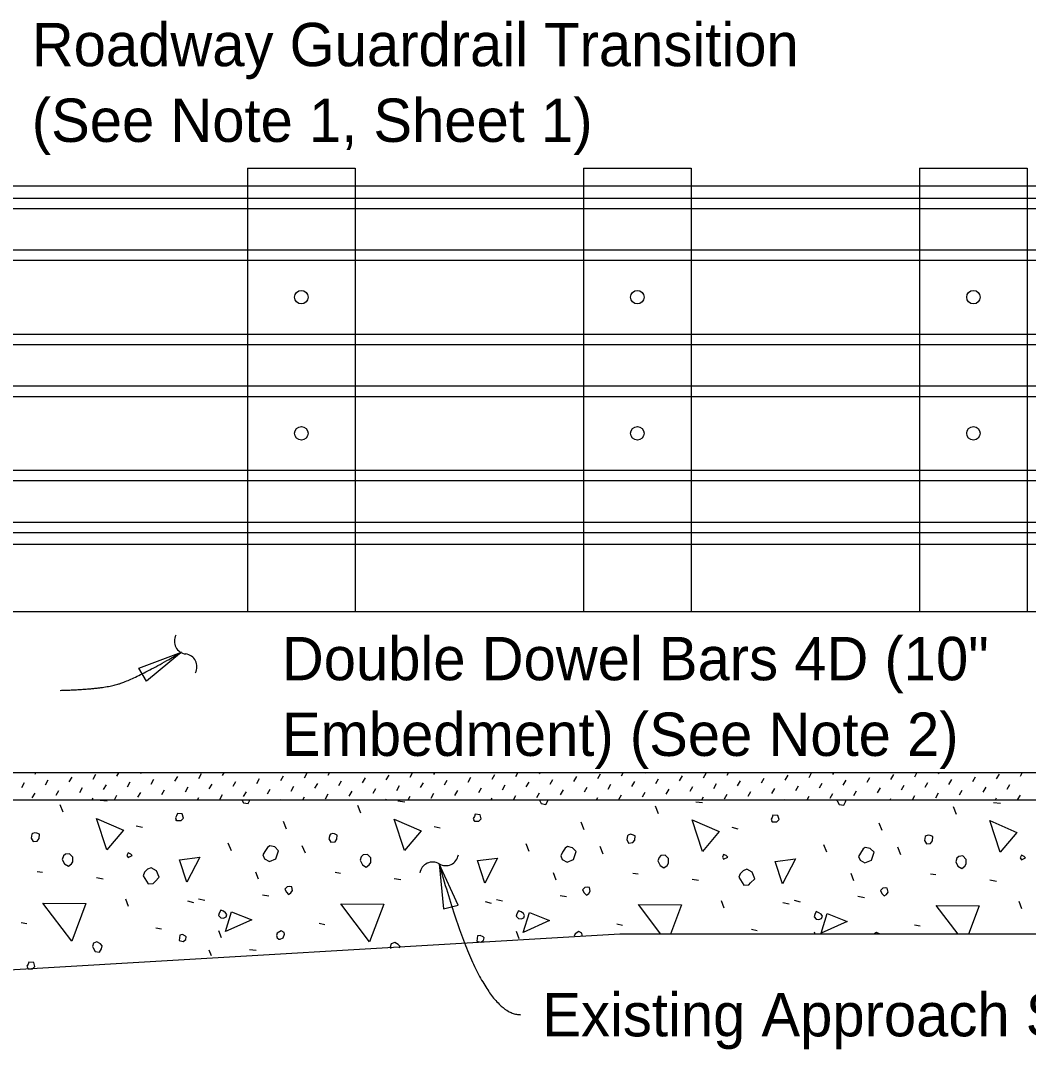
# Model space of a CAD drawing. Extents: x 21526.6 to 21595.9, y 56117 to 56157.3.
# Drawn here: x 21556.736 to 21561.422, y 56133.174 to 56137.959 of the extents above; entities that cross this region are included whole.
import ezdxf

# ---------------------------------------------------------------- set-up
doc = ezdxf.new("R2010")
doc.units = 0
for name, color, linetype in [('AdhocPoint_dp', 7, 'Continuous'), ('Border', 7, 'Continuous'), ('Patterning', 7, 'Continuous'), ('PlotBorder_dp', 7, 'Continuous'), ('SheetBorder_dp', 7, 'Continuous')]:
    doc.layers.add(name, color=color, linetype=linetype)

msp = doc.modelspace()

# ---------------------------------------------------------------- linework, layer by layer
at = {"layer": 'AdhocPoint_dp'}
for p, q in [((21554.3018, 56135.21), (21562.4118, 56135.21)), ((21565.8764, 56134.4601), (21554.3018, 56134.4601)), ((21554.3018, 56134.3351), (21565.8764, 56134.3351)), ((21559.5217, 56133.71), (21555.3017, 56133.4601)), ((21565.8764, 56133.71), (21559.5217, 56133.71))]:
    msp.add_line(p, q, dxfattribs=at)
at = {"layer": 'Patterning'}
for p, q in [((21557.7913, 56137.2725), (21557.7913, 56135.21)), ((21557.7913, 56137.2725), (21558.2913, 56137.2725)), ((21558.2913, 56137.2725), (21558.2913, 56135.21)), ((21559.3538, 56137.2725), (21559.3538, 56135.21)), ((21559.3538, 56137.2725), (21559.8538, 56137.2725)), ((21559.8538, 56137.2725), (21559.8538, 56135.21)), ((21560.9163, 56137.2725), (21560.9163, 56135.21)), ((21560.9163, 56137.2725), (21561.4163, 56137.2725)), ((21561.4163, 56137.2725), (21561.4163, 56135.21)), ((21552.8484, 56137.1336), (21564.1633, 56137.1336)), ((21552.8484, 56137.0853), (21564.1633, 56137.0853)), ((21552.8484, 56136.8925), (21564.1633, 56136.8925)), ((21552.8484, 56136.8443), (21564.1633, 56136.8443)), ((21552.8484, 56136.5003), (21564.1633, 56136.5003)), ((21552.8484, 56136.4521), (21564.1633, 56136.4521)), ((21552.8484, 56136.2593), (21564.1633, 56136.2593)), ((21552.8484, 56136.2112), (21564.1633, 56136.2112)), ((21552.8484, 56135.8672), (21564.1633, 56135.8672)), ((21552.8484, 56135.819), (21564.1633, 56135.819)), ((21552.8484, 56135.6262), (21564.1633, 56135.6262)), ((21552.8484, 56135.5779), (21564.1633, 56135.5779)), ((21556.803, 56134.4539), (21556.8066, 56134.4601)), ((21557.0731, 56134.431), (21557.086, 56134.4534)), ((21557.1837, 56134.4439), (21557.1931, 56134.4601)), ((21557.2943, 56134.4569), (21557.2962, 56134.4601)), ((21557.5644, 56134.434), (21557.5774, 56134.4564)), ((21557.6751, 56134.447), (21557.6827, 56134.4601)), ((21557.7857, 56134.4599), (21557.7858, 56134.4601)), ((21557.9452, 56134.424), (21557.9581, 56134.4464)), ((21558.0558, 56134.437), (21558.0688, 56134.4594)), ((21558.1664, 56134.45), (21558.1723, 56134.4601)), ((21558.4365, 56134.4271), (21558.4495, 56134.4495)), ((21558.5472, 56134.44), (21558.5588, 56134.4601)), ((21558.6578, 56134.453), (21558.6619, 56134.4601)), ((21558.9279, 56134.4301), (21558.9409, 56134.4525)), ((21559.0385, 56134.4431), (21559.0484, 56134.4601)), ((21559.1492, 56134.456), (21559.1515, 56134.4601)), ((21559.4193, 56134.4331), (21559.4322, 56134.4555)), ((21559.5299, 56134.4461), (21559.538, 56134.4601)), ((21559.6405, 56134.459), (21559.6412, 56134.4601)), ((21559.8, 56134.4232), (21559.813, 56134.4456)), ((21559.9106, 56134.4361), (21559.9236, 56134.4585)), ((21560.0213, 56134.4491), (21560.0276, 56134.4601)), ((21560.2914, 56134.4262), (21560.3043, 56134.4486)), ((21560.402, 56134.4391), (21560.4141, 56134.4601)), ((21560.5126, 56134.4521), (21560.5173, 56134.4601)), ((21560.7827, 56134.4292), (21560.7957, 56134.4516)), ((21560.8934, 56134.4422), (21560.9038, 56134.4601)), ((21561.004, 56134.4551), (21561.0069, 56134.4601)), ((21561.2741, 56134.4322), (21561.2871, 56134.4546)), ((21561.3847, 56134.4452), (21561.3934, 56134.4601)), ((21556.7412, 56134.3921), (21556.7541, 56134.4145)), ((21556.8518, 56134.405), (21556.8648, 56134.4274)), ((21556.9624, 56134.418), (21556.9754, 56134.4404)), ((21557.1219, 56134.3821), (21557.1349, 56134.4045)), ((21557.2325, 56134.3951), (21557.2455, 56134.4175)), ((21557.3432, 56134.4081), (21557.3561, 56134.4305)), ((21557.4538, 56134.421), (21557.4668, 56134.4434)), ((21557.6133, 56134.3852), (21557.6262, 56134.4075)), ((21557.7239, 56134.3981), (21557.7369, 56134.4205)), ((21557.8345, 56134.4111), (21557.8475, 56134.4335)), ((21557.994, 56134.3752), (21558.007, 56134.3976)), ((21558.1046, 56134.3882), (21558.1176, 56134.4106)), ((21558.2153, 56134.4011), (21558.2282, 56134.4235)), ((21558.3259, 56134.4141), (21558.3389, 56134.4365)), ((21558.4854, 56134.3782), (21558.4983, 56134.4006)), ((21558.596, 56134.3912), (21558.609, 56134.4136)), ((21558.7066, 56134.4042), (21558.7196, 56134.4266)), ((21558.8173, 56134.4171), (21558.8302, 56134.4395)), ((21558.9767, 56134.3813), (21558.9897, 56134.4036)), ((21559.0874, 56134.3942), (21559.1003, 56134.4166)), ((21559.198, 56134.4072), (21559.211, 56134.4296)), ((21559.3086, 56134.4201), (21559.3216, 56134.4425)), ((21559.4681, 56134.3843), (21559.4811, 56134.4067)), ((21559.5787, 56134.3972), (21559.5917, 56134.4196)), ((21559.6894, 56134.4102), (21559.7023, 56134.4326)), ((21559.9595, 56134.3873), (21559.9724, 56134.4097)), ((21560.0701, 56134.4003), (21560.0831, 56134.4226)), ((21560.1807, 56134.4132), (21560.1937, 56134.4356)), ((21560.3402, 56134.3774), (21560.3532, 56134.3997)), ((21560.4508, 56134.3903), (21560.4638, 56134.4127)), ((21560.5615, 56134.4033), (21560.5744, 56134.4257)), ((21560.6721, 56134.4162), (21560.6851, 56134.4386)), ((21560.8316, 56134.3804), (21560.8445, 56134.4028)), ((21560.9422, 56134.3933), (21560.9552, 56134.4157)), ((21561.0528, 56134.4063), (21561.0658, 56134.4287)), ((21561.1635, 56134.4193), (21561.1764, 56134.4417)), ((21561.3229, 56134.3834), (21561.3359, 56134.4058)), ((21556.79, 56134.3432), (21556.803, 56134.3656)), ((21556.9006, 56134.3562), (21556.9136, 56134.3786)), ((21557.0113, 56134.3692), (21557.0242, 56134.3916)), ((21557.1718, 56134.3351), (21557.1837, 56134.3557)), ((21557.2814, 56134.3463), (21557.2943, 56134.3687)), ((21557.392, 56134.3592), (21557.405, 56134.3816)), ((21557.5026, 56134.3722), (21557.5156, 56134.3946)), ((21557.6621, 56134.3363), (21557.6751, 56134.3587)), ((21557.7727, 56134.3493), (21557.7857, 56134.3717)), ((21557.8834, 56134.3623), (21557.8963, 56134.3846)), ((21558.1535, 56134.3393), (21558.1664, 56134.3617)), ((21558.2641, 56134.3523), (21558.2771, 56134.3747)), ((21558.3747, 56134.3653), (21558.3877, 56134.3877)), ((21558.5375, 56134.3351), (21558.5472, 56134.3518)), ((21558.6448, 56134.3424), (21558.6578, 56134.3648)), ((21558.7555, 56134.3553), (21558.7684, 56134.3777)), ((21558.8661, 56134.3683), (21558.8791, 56134.3907)), ((21559.0271, 56134.3351), (21559.0385, 56134.3548)), ((21559.1362, 56134.3454), (21559.1492, 56134.3678)), ((21559.2468, 56134.3583), (21559.2598, 56134.3807)), ((21559.3575, 56134.3713), (21559.3704, 56134.3937)), ((21559.5169, 56134.3354), (21559.5299, 56134.3578)), ((21559.6276, 56134.3484), (21559.6405, 56134.3708)), ((21559.7382, 56134.3614), (21559.7512, 56134.3838)), ((21559.8488, 56134.3743), (21559.8618, 56134.3967)), ((21560.0083, 56134.3385), (21560.0213, 56134.3609)), ((21560.1189, 56134.3514), (21560.1319, 56134.3738)), ((21560.2296, 56134.3644), (21560.2425, 56134.3868)), ((21560.3928, 56134.3351), (21560.402, 56134.3509)), ((21560.4997, 56134.3415), (21560.5126, 56134.3639)), ((21560.6103, 56134.3544), (21560.6233, 56134.3768)), ((21560.7209, 56134.3674), (21560.7339, 56134.3898)), ((21560.8824, 56134.3351), (21560.8934, 56134.3539)), ((21560.991, 56134.3445), (21561.004, 56134.3669)), ((21561.1017, 56134.3575), (21561.1146, 56134.3799)), ((21561.2123, 56134.3704), (21561.2253, 56134.3928)), ((21561.3721, 56134.3351), (21561.3847, 56134.3569)), ((21556.9334, 56134.2767), (21556.9193, 56134.312)), ((21557.0686, 56134.3351), (21557.0731, 56134.3427)), ((21557.1061, 56134.3326), (21557.1379, 56134.3291)), ((21557.5582, 56134.3351), (21557.5644, 56134.3458)), ((21557.9447, 56134.3351), (21557.9452, 56134.3358)), ((21558.0479, 56134.3351), (21558.0558, 56134.3488)), ((21558.3181, 56134.2732), (21558.304, 56134.3085)), ((21558.4343, 56134.3351), (21558.4365, 56134.3388)), ((21558.4907, 56134.3291), (21558.5225, 56134.3256)), ((21558.924, 56134.3351), (21558.9279, 56134.3418)), ((21559.4136, 56134.3351), (21559.4193, 56134.3449)), ((21559.7028, 56134.2696), (21559.6886, 56134.305)), ((21559.8754, 56134.3256), (21559.9072, 56134.322)), ((21559.9032, 56134.3351), (21559.9106, 56134.3479)), ((21560.2897, 56134.3351), (21560.2914, 56134.3379)), ((21560.7793, 56134.3351), (21560.7827, 56134.341)), ((21561.2601, 56134.322), (21561.2919, 56134.3185)), ((21561.2689, 56134.3351), (21561.2741, 56134.344)), ((21561.0875, 56134.2661), (21561.0733, 56134.3014)), ((21557.274, 56134.2142), (21557.3023, 56134.2071)), ((21557.9723, 56134.1983), (21557.9581, 56134.2336)), ((21558.6587, 56134.2107), (21558.6869, 56134.2036)), ((21559.3569, 56134.1947), (21559.3428, 56134.2301)), ((21560.0433, 56134.2071), (21560.0716, 56134.2001)), ((21560.7416, 56134.1912), (21560.7275, 56134.2266)), ((21557.7159, 56134.0975), (21557.7018, 56134.1329)), ((21558.06, 56134.0858), (21558.0459, 56134.1211)), ((21559.1006, 56134.094), (21559.0865, 56134.1293)), ((21559.4447, 56134.0822), (21559.4306, 56134.1176)), ((21560.4853, 56134.0904), (21560.4711, 56134.1258)), ((21560.8294, 56134.0787), (21560.8152, 56134.1141)), ((21556.8132, 56134.0009), (21556.838, 56133.9974)), ((21557.089, 56133.9726), (21557.1191, 56133.9673)), ((21557.8414, 56133.9649), (21557.8291, 56133.9985)), ((21558.1979, 56133.9974), (21558.2227, 56133.9938)), ((21558.4737, 56133.9691), (21558.5037, 56133.9638)), ((21559.2261, 56133.9614), (21559.2137, 56133.995)), ((21559.5826, 56133.9938), (21559.6073, 56133.9903)), ((21560.6108, 56133.9579), (21560.5984, 56133.9915)), ((21560.9673, 56133.9903), (21560.992, 56133.9868)), ((21559.8584, 56133.9656), (21559.8884, 56133.9603)), ((21561.243, 56133.962), (21561.2731, 56133.9567)), ((21557.2375, 56133.8383), (21557.2251, 56133.8719)), ((21557.5639, 56133.8748), (21557.5922, 56133.8677)), ((21557.8603, 56133.8931), (21557.8903, 56133.8878)), ((21558.9486, 56133.8712), (21558.9769, 56133.8642)), ((21559.2449, 56133.8895), (21559.275, 56133.8842)), ((21560.6296, 56133.886), (21560.6597, 56133.8807)), ((21557.5115, 56133.8648), (21557.5398, 56133.8577)), ((21558.8962, 56133.8613), (21558.9245, 56133.8542)), ((21560.0068, 56133.8312), (21559.9945, 56133.8648)), ((21560.2808, 56133.8577), (21560.3091, 56133.8507)), ((21560.3333, 56133.8677), (21560.3615, 56133.8606)), ((21561.3915, 56133.8277), (21561.3791, 56133.8613)), ((21556.739, 56133.764), (21556.7655, 56133.7587)), ((21557.3648, 56133.7393), (21557.3913, 56133.734)), ((21558.1237, 56133.7605), (21558.1502, 56133.7552)), ((21559.5083, 56133.757), (21559.5349, 56133.7517)), ((21560.1341, 56133.7322), (21560.1606, 56133.7269)), ((21560.893, 56133.7534), (21560.9195, 56133.7481)), ((21557.67, 56133.6922), (21557.6576, 56133.7258)), ((21559.0546, 56133.6887), (21559.0423, 56133.7222)), ((21560.4301, 56133.71), (21560.4269, 56133.7187)), ((21557.624, 56133.6092), (21557.6134, 56133.6358)), ((21557.8002, 56133.6385), (21557.832, 56133.635))]:
    msp.add_line(p, q, dxfattribs=at)
for points in [[(21557.7643, 56134.3351), (21557.7725, 56134.3203), (21557.7937, 56134.3167), (21557.8026, 56134.3326), (21557.8032, 56134.3351)], [(21559.1471, 56134.3351), (21559.1483, 56134.3326)], [(21559.1483, 56134.3326), (21559.1572, 56134.3167), (21559.1784, 56134.3132), (21559.1872, 56134.3291), (21559.1887, 56134.3351)], [(21560.53, 56134.3351), (21560.533, 56134.3291)], [(21560.533, 56134.3291), (21560.5419, 56134.3132), (21560.5631, 56134.3097), (21560.5719, 56134.3256), (21560.5743, 56134.3351)], [(21557.4614, 56134.2389), (21557.4826, 56134.2389), (21557.4932, 56134.2495), (21557.4879, 56134.269), (21557.4649, 56134.2708), (21557.4614, 56134.2602), (21557.4561, 56134.2513), (21557.4614, 56134.2389), (21557.4578, 56134.2425)], [(21558.846, 56134.2354), (21558.8673, 56134.2354), (21558.8779, 56134.246), (21558.8726, 56134.2655), (21558.8496, 56134.2672), (21558.846, 56134.2566), (21558.8407, 56134.2478), (21558.846, 56134.2354), (21558.8425, 56134.2389)], [(21560.2307, 56134.2319), (21560.2519, 56134.2319), (21560.2625, 56134.2425), (21560.2572, 56134.2619), (21560.2343, 56134.2637), (21560.2307, 56134.2531), (21560.2254, 56134.2442), (21560.2307, 56134.2319), (21560.2272, 56134.2354)], [(21557.1367, 56134.1017), (21557.089, 56134.2484), (21557.2145, 56134.1936), (21557.1367, 56134.1017)], [(21558.5214, 56134.0981), (21558.4737, 56134.2449), (21558.5992, 56134.1901), (21558.5214, 56134.0981)], [(21559.9061, 56134.0946), (21559.8584, 56134.2413), (21559.9839, 56134.1865), (21559.9061, 56134.0946)], [(21561.2908, 56134.0911), (21561.243, 56134.2378), (21561.3685, 56134.183), (21561.2908, 56134.0911)], [(21556.7849, 56134.1565), (21556.7938, 56134.1406), (21556.8132, 56134.1423), (21556.8221, 56134.1547), (21556.8238, 56134.1742), (21556.8115, 56134.1795), (21556.8026, 56134.1812), (21556.792, 56134.1777), (21556.7885, 56134.1742), (21556.7849, 56134.1565)], [(21558.1696, 56134.1529), (21558.1785, 56134.137), (21558.1979, 56134.1388), (21558.2067, 56134.1512), (21558.2085, 56134.1706), (21558.1961, 56134.1759), (21558.1873, 56134.1777), (21558.1767, 56134.1742), (21558.1732, 56134.1706), (21558.1696, 56134.1529)], [(21559.5543, 56134.1494), (21559.5631, 56134.1335), (21559.5826, 56134.1353), (21559.5914, 56134.1476), (21559.5932, 56134.1671), (21559.5808, 56134.1724), (21559.572, 56134.1742), (21559.5614, 56134.1706), (21559.5578, 56134.1671), (21559.5543, 56134.1494)], [(21560.939, 56134.1459), (21560.9478, 56134.13), (21560.9673, 56134.1317), (21560.9761, 56134.1441), (21560.9779, 56134.1636), (21560.9655, 56134.1689), (21560.9567, 56134.1706), (21560.946, 56134.1671), (21560.9425, 56134.1636), (21560.939, 56134.1459)], [(21557.8697, 56134.0604), (21557.8927, 56134.048), (21557.9228, 56134.0604), (21557.9351, 56134.0975), (21557.9175, 56134.1152), (21557.8945, 56134.1205), (21557.8839, 56134.1134), (21557.8715, 56134.094), (21557.8627, 56134.0781), (21557.8697, 56134.0604)], [(21559.2544, 56134.0569), (21559.2774, 56134.0445), (21559.3074, 56134.0569), (21559.3198, 56134.094), (21559.3021, 56134.1117), (21559.2792, 56134.117), (21559.2685, 56134.1099), (21559.2562, 56134.0904), (21559.2473, 56134.0745), (21559.2544, 56134.0569)], [(21560.6391, 56134.0533), (21560.6621, 56134.041), (21560.6921, 56134.0533), (21560.7045, 56134.0904), (21560.6868, 56134.1081), (21560.6638, 56134.1134), (21560.6532, 56134.1064), (21560.6408, 56134.0869), (21560.632, 56134.071), (21560.6391, 56134.0533)], [(21556.9299, 56134.0575), (21556.9405, 56134.0363), (21556.9582, 56134.0257), (21556.9723, 56134.0363), (21556.9794, 56134.0469), (21556.9794, 56134.0681), (21556.9635, 56134.084), (21556.944, 56134.0822), (21556.9352, 56134.0734), (21556.9299, 56134.0575)], [(21557.2357, 56134.0663), (21557.2552, 56134.0752), (21557.2481, 56134.0822), (21557.2357, 56134.0875), (21557.2304, 56134.0752), (21557.2357, 56134.0663)], [(21557.5091, 56133.9508), (21557.4755, 56134.0551), (21557.5692, 56134.0675), (21557.5091, 56133.9508)], [(21558.3146, 56134.054), (21558.3252, 56134.0327), (21558.3429, 56134.0221), (21558.357, 56134.0327), (21558.3641, 56134.0433), (21558.3641, 56134.0646), (21558.3482, 56134.0805), (21558.3287, 56134.0787), (21558.3199, 56134.0699), (21558.3146, 56134.054)], [(21558.8938, 56133.9473), (21558.8602, 56134.0516), (21558.9539, 56134.0639), (21558.8938, 56133.9473)], [(21559.6993, 56134.0504), (21559.7099, 56134.0292), (21559.7275, 56134.0186), (21559.7417, 56134.0292), (21559.7488, 56134.0398), (21559.7488, 56134.061), (21559.7328, 56134.0769), (21559.7134, 56134.0752), (21559.7046, 56134.0663), (21559.6993, 56134.0504)], [(21560.0051, 56134.0593), (21560.0245, 56134.0681), (21560.0175, 56134.0752), (21560.0051, 56134.0805), (21559.9998, 56134.0681), (21560.0051, 56134.0593)], [(21561.0839, 56134.0469), (21561.0945, 56134.0257), (21561.1122, 56134.0151), (21561.1264, 56134.0257), (21561.1334, 56134.0363), (21561.1334, 56134.0575), (21561.1175, 56134.0734), (21561.0981, 56134.0716), (21561.0892, 56134.0628), (21561.0839, 56134.0469)], [(21561.3898, 56134.0557), (21561.4092, 56134.0646), (21561.4021, 56134.0716), (21561.3898, 56134.0769), (21561.3845, 56134.0646), (21561.3898, 56134.0557)], [(21557.3064, 56133.9815), (21557.3294, 56133.9444), (21557.3524, 56133.9461), (21557.3612, 56133.955), (21557.3807, 56133.9744), (21557.3683, 56134.0045), (21557.3436, 56134.0186), (21557.3259, 56134.0115), (21557.3117, 56133.9974), (21557.3064, 56133.9815)], [(21560.2785, 56133.9437), (21560.2449, 56134.048), (21560.3386, 56134.0604), (21560.2785, 56133.9437)], [(21560.0758, 56133.9744), (21560.0988, 56133.9373), (21560.1218, 56133.939), (21560.1306, 56133.9479), (21560.15, 56133.9673), (21560.1377, 56133.9974), (21560.1129, 56134.0115), (21560.0952, 56134.0045), (21560.0811, 56133.9903), (21560.0758, 56133.9744)], [(21557.9716, 56133.9055), (21557.9822, 56133.8949), (21557.9928, 56133.9019), (21557.9999, 56133.9125), (21557.9964, 56133.9302), (21557.9875, 56133.932), (21557.9752, 56133.9302), (21557.9646, 56133.9196), (21557.9716, 56133.9055)], [(21559.3563, 56133.9019), (21559.3669, 56133.8913), (21559.3775, 56133.8984), (21559.3846, 56133.909), (21559.3811, 56133.9267), (21559.3722, 56133.9284), (21559.3598, 56133.9267), (21559.3492, 56133.9161), (21559.3563, 56133.9019)], [(21560.741, 56133.8984), (21560.7516, 56133.8878), (21560.7622, 56133.8949), (21560.7693, 56133.9055), (21560.7657, 56133.9231), (21560.7569, 56133.9249), (21560.7445, 56133.9231), (21560.7339, 56133.9125), (21560.741, 56133.8984)], [(21556.9741, 56133.6774), (21556.8397, 56133.8542), (21557.0395, 56133.8524), (21556.9741, 56133.6774)], [(21558.3588, 56133.6739), (21558.2244, 56133.8507), (21558.4242, 56133.8489), (21558.3588, 56133.6739)], [(21559.7133, 56133.71), (21559.6091, 56133.8471), (21559.8089, 56133.8454), (21559.7583, 56133.71)], [(21561.0953, 56133.71), (21560.9938, 56133.8436), (21561.1935, 56133.8418), (21561.1443, 56133.71)], [(21557.6664, 56133.7864), (21557.6788, 56133.7846), (21557.6912, 56133.7899), (21557.6947, 56133.8005), (21557.6894, 56133.8094), (21557.6788, 56133.8164), (21557.6664, 56133.8217), (21557.6594, 56133.8076), (21557.6558, 56133.797), (21557.6664, 56133.7864)], [(21557.6888, 56133.7216), (21557.7171, 56133.8135), (21557.8108, 56133.7764), (21557.6888, 56133.7216)], [(21559.0511, 56133.7829), (21559.0635, 56133.7811), (21559.0759, 56133.7864), (21559.0794, 56133.797), (21559.0741, 56133.8058), (21559.0635, 56133.8129), (21559.0511, 56133.8182), (21559.044, 56133.8041), (21559.0405, 56133.7935), (21559.0511, 56133.7829)], [(21559.0735, 56133.7181), (21559.1017, 56133.81), (21559.1954, 56133.7729), (21559.0735, 56133.7181)], [(21560.4358, 56133.7793), (21560.4482, 56133.7776), (21560.4605, 56133.7829), (21560.4641, 56133.7935), (21560.4588, 56133.8023), (21560.4482, 56133.8094), (21560.4358, 56133.8147), (21560.4287, 56133.8005), (21560.4252, 56133.7899), (21560.4358, 56133.7793)], [(21560.4581, 56133.7145), (21560.4864, 56133.8065), (21560.5801, 56133.7693), (21560.4581, 56133.7145)], [(21557.4726, 56133.681), (21557.492, 56133.6756), (21557.5044, 56133.6845), (21557.5062, 56133.6969), (21557.5027, 56133.7004), (21557.4885, 56133.7075), (21557.4761, 56133.7057), (21557.4744, 56133.6933), (21557.4726, 56133.681)], [(21557.9363, 56133.6863), (21557.9433, 56133.6863), (21557.9575, 56133.6933), (21557.9628, 56133.7092), (21557.961, 56133.7181), (21557.9469, 56133.7251), (21557.9292, 56133.7145), (21557.9257, 56133.7039), (21557.9292, 56133.6933), (21557.9363, 56133.6863)], [(21558.8573, 56133.6774), (21558.8767, 56133.6721), (21558.8891, 56133.681), (21558.8909, 56133.6933), (21558.8873, 56133.6969), (21558.8732, 56133.7039), (21558.8608, 56133.7022), (21558.859, 56133.6898), (21558.8573, 56133.6774)], [(21559.3452, 56133.699), (21559.3475, 56133.7057), (21559.3457, 56133.7145), (21559.3316, 56133.7216), (21559.3139, 56133.711), (21559.3103, 56133.7004), (21559.3115, 56133.6969)], [(21560.7306, 56133.71), (21560.7304, 56133.711), (21560.7162, 56133.7181), (21560.7028, 56133.71)], [(21557.0731, 56133.6456), (21557.0819, 56133.6297), (21557.1031, 56133.6262), (21557.112, 56133.6421), (21557.1155, 56133.6562), (21557.1067, 56133.665), (21557.0908, 56133.6739), (21557.0749, 56133.6686), (21557.0696, 56133.6527), (21557.0731, 56133.6456)], [(21558.4985, 56133.6461), (21558.5002, 56133.6527), (21558.4914, 56133.6615), (21558.4754, 56133.6703), (21558.4595, 56133.665), (21558.4542, 56133.6491), (21558.4571, 56133.6435)], [(21556.7708, 56133.5484), (21556.792, 56133.5484), (21556.8026, 56133.559), (21556.7973, 56133.5784), (21556.7743, 56133.5802), (21556.7708, 56133.5696), (21556.7655, 56133.5607), (21556.7708, 56133.5484), (21556.7673, 56133.5519)]]:
    msp.add_lwpolyline(points, dxfattribs=at)
at = {"layer": 'PlotBorder_dp'}
for points in [[(21557.4838, 56135.0207), (21557.3212, 56134.8859), (21557.2858, 56134.947)], [(21558.6823, 56134.0371), (21558.7024, 56133.8269), (21558.7706, 56133.8452)]]:
    msp.add_lwpolyline(points, close=True, dxfattribs=at)
for centre, start, end in [((21557.5105, 56135.0721), 151.5267, 263.2539), ((21557.4965, 56134.9537), 331.5267, 83.2539), ((21558.7125, 56134.0879), 239.2651, 350.9923), ((21558.6515, 56133.9854), 59.2651, 170.9923)]:
    msp.add_arc(centre, 0.0596, start, end, dxfattribs=at)
for points in [[(21556.9198, 56134.8437), (21557.1008, 56134.8486), (21557.2597, 56134.8911), (21557.4838, 56135.0207)], [(21558.6827, 56134.0369), (21558.8719, 56133.3352), (21559.061, 56133.3352)]]:
    msp.add_open_spline(points, degree=2, dxfattribs=at)
at = {"layer": 'SheetBorder_dp'}
for p, q in [((21564.1633, 56137.1891), (21552.8484, 56137.1891)), ((21564.1633, 56135.5224), (21552.8484, 56135.5224))]:
    msp.add_line(p, q, dxfattribs=at)
for centre in [(21558.0413, 56136.6724), (21559.6038, 56136.6724), (21561.1663, 56136.6724), (21558.0413, 56136.0393), (21559.6038, 56136.0393), (21561.1663, 56136.0393)]:
    msp.add_circle(centre, 0.0312, dxfattribs=at)

# ---------------------------------------------------------------- texts
at = {"layer": 'Border'}
msp.add_text('Existing Approach Slab', height=0.2016, dxfattribs=at).set_placement((21559.1619, 56133.2344))
at = {"layer": 'PlotBorder_dp'}
for s, p in [('Roadway Guardrail Transition', (21556.788, 56137.7466)), ('(See Note 1, Sheet 1)', (21556.788, 56137.3946)), ('Double Dowel Bars 4D (10" ', (21557.9507, 56134.8907)), ('Embedment) (See Note 2)', (21557.9507, 56134.5387))]:
    msp.add_text(s, height=0.2016, dxfattribs=at).set_placement(p)

doc.saveas('drawing.dxf')
